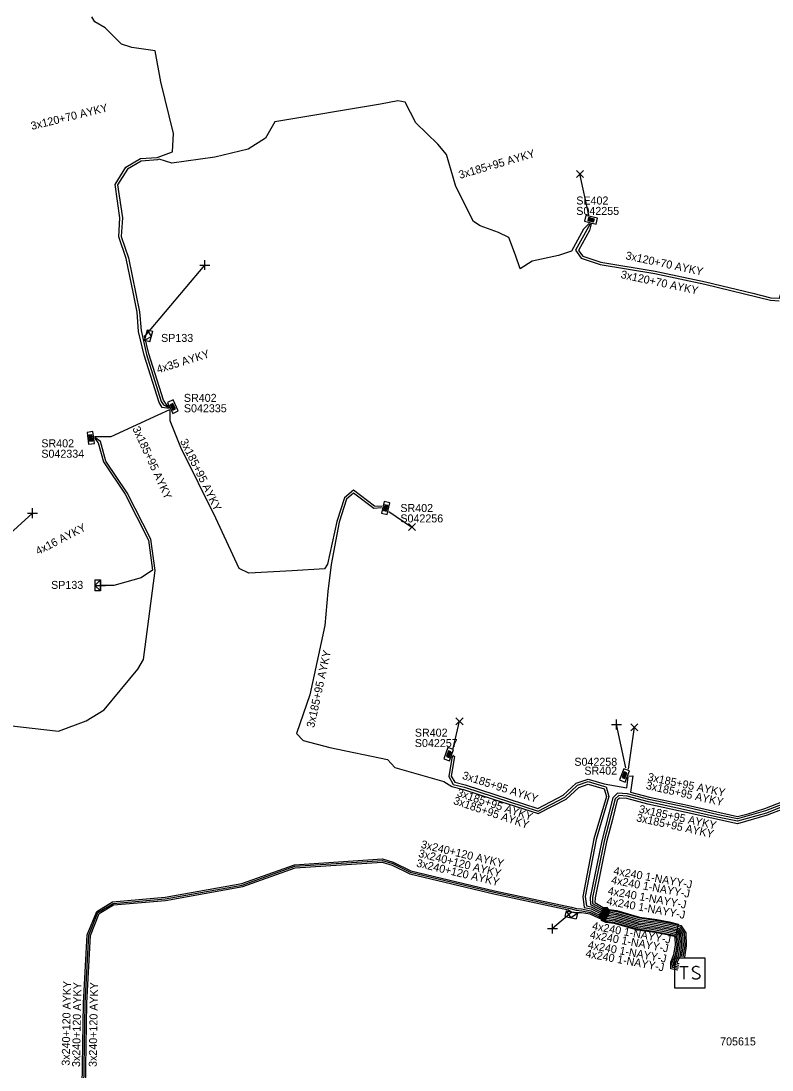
# Model space of a CAD drawing. Extents: x -748492 to -735633, y -1146251 to -1139940.
# Drawn here: x -736689.1 to -736595.2, y -1144893.5 to -1144762.4 of the extents above; entities that cross this region are included whole.
import ezdxf

# ---------------------------------------------------------------- set-up
doc = ezdxf.new("R2010")
doc.units = 0
for name, color, linetype in [('Vrstva 1', 7, 'Continuous'), ('Vrstva 19', 7, 'Continuous'), ('Vrstva 20', 7, 'Continuous'), ('Vrstva 25', 7, 'Continuous'), ('Vrstva 26', 7, 'Continuous'), ('Vrstva 28', 7, 'Continuous'), ('Vrstva 29', 7, 'Continuous'), ('Vrstva 30', 7, 'Continuous'), ('Vrstva 31', 7, 'Continuous'), ('Vrstva 33', 7, 'Continuous'), ('Vrstva 34', 7, 'Continuous'), ('Vrstva 4', 7, 'Continuous'), ('Vrstva 5', 7, 'Continuous'), ('Vrstva 52', 7, 'Continuous'), ('Vrstva 54', 7, 'Continuous'), ('Vrstva 59', 7, 'Continuous'), ('Vrstva 6', 7, 'Continuous'), ('Vrstva 8', 7, 'Continuous'), ('Vrstva 9', 7, 'Continuous')]:
    doc.layers.add(name, color=color, linetype=linetype)

# ---------------------------------------------------------------- blocks, each defined once
blk = doc.blocks.new('NN870')
at = {"layer": 'Vrstva 4'}
for points in [[(0, -0.25), (0.5, 0), (0, 0.25), (-0.5, 0), (0, -0.25)], [(0.37, 0), (0, 0.19), (-0.36, 0), (0, -0.19), (0.37, 0)], [(0.24, 0), (0, 0.12), (-0.25, 0), (0, -0.12), (0.24, 0)], [(0.12, 0), (0, 0.06), (-0.13, 0), (0, -0.06), (0.12, 0)]]:
    blk.add_lwpolyline(points, dxfattribs=at)
blk = doc.blocks.new('NN800')
at = {"layer": 'Vrstva 1'}
for points in [[(-0.44, 0.44), (0.44, -0.44)], [(-0.44, -0.44), (0.44, 0.44)]]:
    blk.add_lwpolyline(points, dxfattribs=at)
blk = doc.blocks.new('NN620')
at = {"layer": 'Vrstva 8'}
for points in [[(0.75, 0), (-0.75, 0)], [(-0.75, 0), (-0.75, -0.75)], [(0.75, -0.75), (0.75, 0)], [(-0.75, -0.75), (0.75, -0.75)], [(0.37, -0.18), (-0.38, -0.18)], [(-0.38, -0.18), (-0.38, -0.56)], [(-0.38, -0.56), (0.37, -0.56)], [(0.32, -0.23), (-0.33, -0.23)], [(-0.33, -0.23), (-0.33, -0.51)], [(-0.33, -0.51), (0.32, -0.51)], [(0.27, -0.27), (-0.28, -0.27)], [(-0.28, -0.27), (-0.28, -0.46)], [(-0.28, -0.46), (0.27, -0.46)], [(0.23, -0.32), (-0.23, -0.32)], [(-0.23, -0.32), (-0.23, -0.42)], [(-0.23, -0.42), (0.23, -0.42)], [(-0.19, -0.37), (0.19, -0.37)], [(0.23, -0.42), (0.23, -0.32)], [(0.27, -0.46), (0.27, -0.27)], [(0.32, -0.51), (0.32, -0.23)], [(0.37, -0.56), (0.37, -0.18)]]:
    blk.add_lwpolyline(points, dxfattribs=at)
blk = doc.blocks.new('NN630')
at = {"layer": 'Vrstva 9'}
for points in [[(0, -0.7), (-0.7, 0)], [(-0.7, -0.7), (-0.7, 0), (0.7, 0), (0.7, -0.7)], [(-0.7, -0.7), (0.7, -0.7)], [(0, -0.7), (0.7, 0)]]:
    blk.add_lwpolyline(points, dxfattribs=at)
blk = doc.blocks.new('NN640')
at = {"layer": 'Vrstva 6'}
for points in [[(-1.89, 1.89), (1.89, 1.89)], [(-1.89, -1.89), (-1.89, 1.89)], [(1.89, 1.89), (1.89, -1.89)], [(-1.26, 0.79), (-0.22, 0.79)], [(-0.73, 0.79), (-0.73, -0.79)], [(1.2, 0.66), (0.94, 0.79), (0.66, 0.79), (0.41, 0.66), (0.28, 0.47), (0.28, 0.41), (0.41, 0.22), (1.13, -0.16), (1.26, -0.32), (1.26, -0.47), (1.13, -0.66), (0.91, -0.79), (0.63, -0.79), (0.5, -0.73), (0.28, -0.6)], [(1.89, -1.89), (-1.89, -1.89)]]:
    blk.add_lwpolyline(points, dxfattribs=at)

msp = doc.modelspace()

# ---------------------------------------------------------------- linework, layer by layer
at = {"layer": 'Vrstva 20'}
msp.add_lwpolyline([(-736607.29, -1144876.83), (-736608.36, -1144876.57), (-736609.87, -1144876.29), (-736612.07, -1144875.98), (-736614.92, -1144875.17), (-736616.01, -1144875.02), (-736616.56, -1144874.77), (-736616.09, -1144873.22), (-736615.66, -1144873.41), (-736614.65, -1144873.55), (-736611.8, -1144874.36), (-736609.64, -1144874.67), (-736608.09, -1144874.96), (-736606.99, -1144875.22)], close=True, dxfattribs=at)
at = {"layer": 'Vrstva 5'}
for points in [[(-736670.58, -1144810.81), (-736671.47, -1144810.69), (-736671.87, -1144810.05), (-736673.71, -1144804.14), (-736674.45, -1144801.18), (-736674.59, -1144798.78), (-736675.07, -1144796.49), (-736675.96, -1144792.06), (-736676.9, -1144789.34), (-736676.75, -1144786.99), (-736677.37, -1144782.8), (-736676.01, -1144780.67), (-736674.18, -1144779.59), (-736672.12, -1144779.45), (-736670.19, -1144778.72), (-736670.05, -1144776.44), (-736671.63, -1144770), (-736672.37, -1144766.1), (-736675.28, -1144765.69), (-736676.55, -1144765.27), (-736678.61, -1144763.26), (-736679.89, -1144762.49), (-736680.26, -1144761.88)], [(-736618.11, -1144787.69), (-736618.79, -1144788.4), (-736620.3, -1144791.14), (-736621.94, -1144791.69), (-736625.23, -1144792.39), (-736626.71, -1144793.35), (-736627.32, -1144791.63), (-736628.13, -1144789.43), (-736629.45, -1144788.83), (-736631.71, -1144787.98), (-736632.54, -1144787.44), (-736634.78, -1144783.08), (-736635.95, -1144779.06), (-736637.02, -1144777.77), (-736639.77, -1144775.13), (-736641.08, -1144772.53), (-736642.01, -1144772.36), (-736644.19, -1144772.78), (-736657.4, -1144775), (-736658.55, -1144777.03), (-736660.73, -1144778.41), (-736664.91, -1144779.41), (-736670.25, -1144780.14), (-736671.86, -1144779.65), (-736672.05, -1144779.74), (-736674.08, -1144779.89), (-736675.79, -1144780.89), (-736677.05, -1144782.86), (-736676.45, -1144786.97), (-736676.6, -1144789.3), (-736675.68, -1144791.98), (-736674.29, -1144798.72), (-736674.1, -1144801.07), (-736673.42, -1144804.06), (-736671.6, -1144809.92), (-736671.3, -1144810.35), (-736670.64, -1144810.69)], [(-736617.98, -1144787.72), (-736619.81, -1144791.03), (-736619.09, -1144792.02), (-736616.72, -1144792.81), (-736609.9, -1144793.93), (-736603.63, -1144795.28), (-736595.45, -1144797.27), (-736594.33, -1144797.34)], [(-736617.85, -1144787.75), (-736618.05, -1144788.55), (-736619.45, -1144791.05), (-736618.91, -1144791.76), (-736616.64, -1144792.51), (-736609.84, -1144793.63), (-736603.57, -1144794.98), (-736597.64, -1144796.39), (-736595.41, -1144796.97), (-736594.31, -1144797.04), (-736593.31, -1144793.6), (-736593.78, -1144797.23), (-736592.02, -1144797.88), (-736586.01, -1144799.21), (-736576.41, -1144801.48), (-736570.34, -1144802.77), (-736568.81, -1144799.74)], [(-736679.92, -1144814.29), (-736677.87, -1144814.31), (-736671.98, -1144811.6), (-736670.52, -1144810.92)], [(-736644.02, -1144823.07), (-736644.93, -1144823), (-736647.56, -1144821.01), (-736648.69, -1144821.96), (-736649.64, -1144824.94), (-736650.79, -1144830.26), (-736651.17, -1144830.83), (-736655.21, -1144831.08), (-736660.66, -1144831.38), (-736661.86, -1144830.8), (-736664.78, -1144824.51), (-736669.15, -1144815.67), (-736670.49, -1144812.33), (-736670.46, -1144811.04)], [(-736761.09, -1144841.39), (-736760.78, -1144841.99), (-736759.17, -1144842.04), (-736750.14, -1144844.69), (-736741.44, -1144845.96), (-736725.38, -1144847.25), (-736714.55, -1144847.88), (-736711.66, -1144847.99), (-736711.52, -1144846.24), (-736711.16, -1144845.19), (-736711.36, -1144848.01), (-736709.95, -1144848.44), (-736701.65, -1144849.16), (-736684.43, -1144851.13), (-736680.99, -1144849.84), (-736678.74, -1144848.46), (-736674.53, -1144843.36), (-736673.79, -1144842.16), (-736672.37, -1144831.05), (-736672.88, -1144827.15), (-736675.86, -1144821.36), (-736678.52, -1144817.37), (-736679.2, -1144814.95), (-736679.9, -1144814.42)], [(-736644.05, -1144823.2), (-736645.03, -1144823.3), (-736647.54, -1144821.39), (-736648.43, -1144822.14), (-736649.34, -1144825.02), (-736650.34, -1144830.31), (-736650.77, -1144833.69), (-736651.13, -1144837.91), (-736651.6, -1144840.05), (-736653.03, -1144846.58), (-736654.69, -1144851.4), (-736653.87, -1144852.3), (-736650.52, -1144853.18), (-736643.32, -1144854.67), (-736642.38, -1144855.65), (-736636.25, -1144857.41), (-736635.27, -1144858.03), (-736633.79, -1144858.42), (-736630.08, -1144859.61), (-736624.47, -1144861.43), (-736620.98, -1144859.61), (-736619.41, -1144858.16), (-736618.22, -1144857.74), (-736616.24, -1144858.31), (-736615.95, -1144859.27), (-736617.52, -1144864.57), (-736618.89, -1144871.79), (-736618.73, -1144873.15), (-736617.87, -1144873.33), (-736616.28, -1144874.13)], [(-736635.2, -1144854.24), (-736635.25, -1144854.48), (-736635.64, -1144856.8), (-736635.08, -1144857.77), (-736633.7, -1144858.13), (-736629.99, -1144859.33), (-736624.49, -1144861.1), (-736621.15, -1144859.37), (-736619.57, -1144857.89), (-736618.22, -1144857.42), (-736616.3, -1144858), (-736615.98, -1144858.07), (-736615.63, -1144859.27), (-736617.22, -1144864.65), (-736618.59, -1144871.8), (-736618.45, -1144872.93), (-736617.85, -1144873.08), (-736616.2, -1144873.95)], [(-736635.16, -1144854.12), (-736634.92, -1144854.3), (-736635.33, -1144856.74), (-736634.88, -1144857.51), (-736633.62, -1144857.84), (-736629.9, -1144859.04), (-736624.52, -1144860.78), (-736621.33, -1144859.12), (-736619.73, -1144857.63), (-736618.23, -1144857.11), (-736616.23, -1144857.71), (-736613.39, -1144858.19), (-736613.23, -1144856.87)], [(-736613.19, -1144856.75), (-736612.66, -1144856.71), (-736612.95, -1144858.73), (-736610.56, -1144859.39), (-736605.8, -1144860.39), (-736599.57, -1144861.77), (-736598.24, -1144861.44), (-736596.15, -1144860.78), (-736593.91, -1144859.91), (-736591.07, -1144860.91), (-736587.05, -1144861.89), (-736586.45, -1144861.25), (-736585.84, -1144858.49), (-736586.05, -1144858.34)], [(-736586.02, -1144858.22), (-736585.51, -1144858.39), (-736586.17, -1144861.4), (-736586.95, -1144862.22), (-736591.16, -1144861.2), (-736593.9, -1144860.23), (-736596.05, -1144861.06), (-736599.57, -1144862.08), (-736601.98, -1144861.57), (-736605.86, -1144860.68), (-736610.63, -1144859.68), (-736613.29, -1144858.95), (-736614.54, -1144858.89), (-736615.13, -1144859.44), (-736616.52, -1144864.82), (-736617.97, -1144871.89), (-736617.95, -1144872.78), (-736616.11, -1144873.76)], [(-736593.9, -1144860.55), (-736595.95, -1144861.35), (-736599.56, -1144862.39), (-736602.04, -1144861.86), (-736605.93, -1144860.98), (-736610.7, -1144859.97), (-736613.33, -1144859.25), (-736614.4, -1144859.17), (-736614.87, -1144859.6), (-736616.22, -1144864.88), (-736617.67, -1144871.92), (-736617.69, -1144872.67), (-736616.03, -1144873.58)], [(-736558.85, -1144859.73), (-736558.46, -1144861.09), (-736562.04, -1144865.38), (-736563.53, -1144867.52), (-736568.72, -1144866.68), (-736578.62, -1144864.18), (-736584.72, -1144862.86), (-736586.37, -1144862.51), (-736586.75, -1144862.89), (-736591.33, -1144861.77), (-736593.89, -1144860.87), (-736595.86, -1144861.63), (-736599.54, -1144862.7), (-736605.99, -1144861.27), (-736610.77, -1144860.26), (-736613.38, -1144859.55), (-736614.32, -1144859.5), (-736614.6, -1144859.76), (-736615.19, -1144862.17), (-736615.93, -1144864.95), (-736617.36, -1144871.94), (-736617.38, -1144872.55), (-736615.95, -1144873.4)], [(-736679.86, -1144906.22), (-736680.09, -1144905.34), (-736682, -1144897.49), (-736681.74, -1144896.65), (-736681.46, -1144895.96), (-736681.06, -1144895.78), (-736680.89, -1144885.11), (-736680.45, -1144876.64), (-736679.34, -1144873.92), (-736677.56, -1144872.83), (-736671.06, -1144872.27), (-736661.41, -1144870.54), (-736654.87, -1144868.21), (-736643.97, -1144867.49), (-736642.73, -1144867.86), (-736640.53, -1144868.94), (-736630.03, -1144871.44), (-736620.68, -1144873.44), (-736620.25, -1144873.73)], [(-736681.76, -1144895.67), (-736681.46, -1144895.52), (-736681.29, -1144885.09), (-736680.85, -1144876.56), (-736679.66, -1144873.64), (-736677.68, -1144872.45), (-736671.12, -1144871.87), (-736661.51, -1144870.16), (-736654.95, -1144867.81), (-736643.93, -1144867.09), (-736642.59, -1144867.48), (-736640.39, -1144868.56), (-736629.93, -1144871.06), (-736620.3, -1144873.12), (-736619.68, -1144873.29), (-736619.05, -1144873.34), (-736617.9, -1144873.57), (-736616.36, -1144874.31)], [(-736681.73, -1144895.89), (-736681.26, -1144895.65), (-736681.09, -1144885.1), (-736680.65, -1144876.6), (-736679.5, -1144873.78), (-736677.62, -1144872.64), (-736671.09, -1144872.07), (-736661.46, -1144870.35), (-736654.91, -1144868.01), (-736643.95, -1144867.29), (-736642.66, -1144867.67), (-736640.46, -1144868.75), (-736629.98, -1144871.25), (-736620.49, -1144873.28), (-736619.72, -1144873.51), (-736619.01, -1144873.59), (-736617.94, -1144873.79), (-736616.44, -1144874.49)], [(-736606.15, -1144879.37), (-736605.92, -1144877.96), (-736605.99, -1144876.31), (-736606.56, -1144875.46), (-736607.38, -1144875.27), (-736608.05, -1144875.1), (-736609.62, -1144874.81), (-736610.4, -1144874.69), (-736611.77, -1144874.51), (-736614.61, -1144873.7), (-736615.59, -1144873.56), (-736615.95, -1144873.4)], [(-736607.03, -1144880.99), (-736607.89, -1144880.84), (-736607.91, -1144879.97), (-736607.52, -1144879.04), (-736607.32, -1144877.88), (-736607.37, -1144876.94), (-736607.42, -1144876.69), (-736607.7, -1144876.63), (-736608.34, -1144876.47), (-736609.86, -1144876.19), (-736610.6, -1144876.08), (-736612.05, -1144875.88), (-736614.9, -1144875.07), (-736615.98, -1144874.92), (-736617.99, -1144874.01), (-736619.05, -1144873.82), (-736619.66, -1144873.81), (-736620.25, -1144873.73)], [(-736606.98, -1144880.79), (-736607.7, -1144880.67), (-736607.71, -1144880.01), (-736607.32, -1144879.09), (-736607.12, -1144877.89), (-736607.18, -1144876.69), (-736607.29, -1144876.52), (-736607.66, -1144876.44), (-736608.3, -1144876.28), (-736609.82, -1144876), (-736610.57, -1144875.88), (-736612.01, -1144875.69), (-736614.86, -1144874.88), (-736615.93, -1144874.72), (-736616.44, -1144874.49)], [(-736606.95, -1144880.6), (-736607.5, -1144880.5), (-736607.51, -1144880.05), (-736607.13, -1144879.15), (-736606.92, -1144877.9), (-736606.98, -1144876.63), (-736607.17, -1144876.34), (-736607.61, -1144876.24), (-736608.26, -1144876.08), (-736609.79, -1144875.8), (-736610.54, -1144875.68), (-736611.97, -1144875.49), (-736614.82, -1144874.68), (-736615.87, -1144874.53), (-736616.36, -1144874.31)], [(-736606.89, -1144880.41), (-736607.3, -1144880.33), (-736607.31, -1144880.09), (-736606.94, -1144879.21), (-736606.72, -1144877.91), (-736606.78, -1144876.57), (-736607.05, -1144876.16), (-736607.56, -1144876.04), (-736608.22, -1144875.88), (-736609.76, -1144875.6), (-736610.51, -1144875.48), (-736611.93, -1144875.29), (-736614.78, -1144874.48), (-736615.81, -1144874.34), (-736616.28, -1144874.13)], [(-736606.84, -1144880.21), (-736607.11, -1144880.16), (-736607.04, -1144879.96), (-736606.74, -1144879.26), (-736606.52, -1144877.92), (-736606.59, -1144876.5), (-736606.92, -1144875.99), (-736607.52, -1144875.85), (-736608.18, -1144875.69), (-736609.72, -1144875.41), (-736610.48, -1144875.28), (-736611.89, -1144875.1), (-736614.74, -1144874.29), (-736615.76, -1144874.14), (-736616.2, -1144873.95)], [(-736606.54, -1144879.26), (-736606.32, -1144877.94), (-736606.39, -1144876.44), (-736606.8, -1144875.81), (-736607.47, -1144875.66), (-736608.13, -1144875.49), (-736609.69, -1144875.21), (-736610.45, -1144875.09), (-736611.85, -1144874.9), (-736614.7, -1144874.09), (-736615.7, -1144873.95), (-736616.11, -1144873.76)], [(-736606.35, -1144879.32), (-736606.12, -1144877.95), (-736606.19, -1144876.37), (-736606.68, -1144875.63), (-736607.43, -1144875.46), (-736608.09, -1144875.3), (-736609.66, -1144875.01), (-736610.42, -1144874.89), (-736611.81, -1144874.71), (-736614.65, -1144873.9), (-736615.65, -1144873.75), (-736616.03, -1144873.58)]]:
    msp.add_lwpolyline(points, dxfattribs=at)
at = {"layer": 'Vrstva 52'}
for points in [[(-736670.69, -1144810.57), (-736670.9, -1144810.41), (-736671.32, -1144809.78), (-736673.14, -1144803.98), (-736673.69, -1144801.74), (-736673.5, -1144801.64)], [(-736679.89, -1144814.55), (-736679.46, -1144815.11), (-736678.8, -1144817.49), (-736676.12, -1144821.52), (-736673.17, -1144827.24), (-736672.67, -1144831.01), (-736674.1, -1144831.97), (-736677.52, -1144832.94), (-736679.18, -1144832.91)]]:
    msp.add_lwpolyline(points, dxfattribs=at)
at = {"layer": 'Vrstva 59'}
for points in [[(-736618.15, -1144786.64), (-736619.25, -1144781.5)], [(-736673.5, -1144801.64), (-736666.13, -1144792.88)], [(-736711.16, -1144845.19), (-736687.69, -1144823.88)], [(-736643.13, -1144823.69), (-736640.25, -1144825.63)], [(-736635.1, -1144853.28), (-736634.31, -1144849.88)], [(-736613.5, -1144855.7), (-736614.7, -1144850.3)], [(-736613.2, -1144855.88), (-736612.44, -1144850.63)], [(-736620.25, -1144873.73), (-736622.7, -1144875.8)]]:
    msp.add_lwpolyline(points, dxfattribs=at)

# ---------------------------------------------------------------- block references
at = {"layer": 'Vrstva 19'}
for p, rotation in [((-736616.11, -1144873.76), -25.11355997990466), ((-736616.01, -1144873.58), -27.409296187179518), ((-736615.95, -1144873.4), -24.947774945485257), ((-736616.44, -1144874.49), -22.511684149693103), ((-736616.4, -1144874.29), -25.869487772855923), ((-736616.29, -1144874.13), -22.874902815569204), ((-736616.2, -1144873.95), -23.60357793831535)]:
    msp.add_blockref('NN870', p, dxfattribs=dict(at, rotation=rotation))
at = {"layer": 'Vrstva 25'}
msp.add_blockref('NN640', (-736605.52, -1144881.33), dxfattribs=at)
at = {"layer": 'Vrstva 28'}
for p, rotation in [((-736617.95, -1144787.59), 166.57176959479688), ((-736670.46, -1144810.75), 116.30779160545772), ((-736680.03, -1144814.44), -82.83727780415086), ((-736643.91, -1144823.16), 77.313713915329), ((-736635.3, -1144854.14), -109.563783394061), ((-736613.33, -1144856.77), -109.56378334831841)]:
    msp.add_blockref('NN620', p, dxfattribs=dict(at, rotation=rotation))
at = {"layer": 'Vrstva 31'}
for p, rotation in [((-736673.5, -1144801.64), 75.25643607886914), ((-736679.18, -1144832.91), -90.43139438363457), ((-736620.25, -1144873.73), -12.248921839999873)]:
    msp.add_blockref('NN630', p, dxfattribs=dict(at, rotation=rotation))
at = {"layer": 'Vrstva 34'}
for p in [(-736619.25, -1144781.5), (-736640.25, -1144825.63), (-736634.31, -1144849.88), (-736612.44, -1144850.63)]:
    msp.add_blockref('NN800', p, dxfattribs=at)
for p, rotation in [((-736666.13, -1144792.88), 45), ((-736687.69, -1144823.88), 44.99999995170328), ((-736679.18, -1144832.91), 45), ((-736614.7, -1144850.3), 44.99999995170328), ((-736622.7, -1144875.8), 44.99999995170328)]:
    msp.add_blockref('NN800', p, dxfattribs=dict(at, rotation=rotation))

# ---------------------------------------------------------------- texts
at = {"layer": 'Vrstva 26'}
msp.add_text('705615', height=1, dxfattribs=at).set_placement((-736601.73, -1144890.39))
at = {"layer": 'Vrstva 29'}
for s, p in [('S042255', (-736619.71, -1144786.62)), ('S042335', (-736668.76, -1144811.28)), ('S042334', (-736686.58, -1144816.96)), ('S042256', (-736641.7, -1144825.04)), ('S042257', (-736639.89, -1144853.11)), ('S042258', (-736619.95, -1144855.45))]:
    msp.add_text(s, height=1, dxfattribs=at).set_placement(p)
at = {"layer": 'Vrstva 30'}
for s, p in [('SE402', (-736619.71, -1144785.32)), ('SR402', (-736668.76, -1144809.98)), ('SR402', (-736686.58, -1144815.66)), ('SR402', (-736641.7, -1144823.74)), ('SR402', (-736639.89, -1144851.81)), ('SR402', (-736618.7, -1144856.56))]:
    msp.add_text(s, height=1, dxfattribs=at).set_placement(p)
at = {"layer": 'Vrstva 33'}
for p in [(-736671.61, -1144802.49), (-736685.36, -1144833.35)]:
    msp.add_text('SP133', height=1, dxfattribs=at).set_placement(p)
at = {"layer": 'Vrstva 54'}
for s, rotation, p in [('4x35 AYKY', 17.344, (-736672, -1144806.43)), ('4x16 AYKY', 27.317, (-736686.98, -1144829.14))]:
    msp.add_text(s, height=1, rotation=rotation, dxfattribs=at).set_placement(p)
at = {"layer": 'Vrstva 6'}
for s, rotation, p in [('3x120+70 AYKY', 13.786, (-736687.76, -1144776.01)), ('3x185+95 AYKY', 16.232, (-736634.25, -1144782.12)), ('3x120+70 AYKY', 347.852, (-736613.61, -1144792.14)), ('3x120+70 AYKY', 347.847, (-736614.21, -1144794.5)), ('3x185+95 AYKY', 294.707, (-736675.22, -1144813.31)), ('3x185+95 AYKY', 296.305, (-736669.27, -1144814.89)), ('3x185+95 AYKY', 77.648, (-736652.48, -1144850.76)), ('3x185+95 AYKY', 342.121, (-736634.05, -1144857.06)), ('3x185+95 AYKY', 348.135, (-736610.85, -1144857.29)), ('3x185+95 AYKY', 347.344, (-736611.06, -1144858.34)), ('3x185+95 AYKY', 341.519, (-736634.71, -1144859.21)), ('3x185+95 AYKY', 341.523, (-736635.15, -1144860.21)), ('3x185+95 AYKY', 347.636, (-736612.27, -1144862.37)), ('3x185+95 AYKY', 347.638, (-736611.95, -1144861.29)), ('3x240+120 AYKY', 346.586, (-736639.2, -1144865.7)), ('3x240+120 AYKY', 345.896, (-736639.51, -1144866.82)), ('3x240+120 AYKY', 346.579, (-736639.76, -1144868.04)), ('4x240 1-NAYY-J', 349.682, (-736615.11, -1144869.02)), ('4x240 1-NAYY-J', 349.666, (-736615.4, -1144870.17)), ('4x240 1-NAYY-J', 349.643, (-736615.83, -1144871.52)), ('4x240 1-NAYY-J', 349.663, (-736615.98, -1144872.8)), ('4x240 1-NAYY-J', 349.646, (-736617.78, -1144875.9)), ('4x240 1-NAYY-J', 349.629, (-736618.07, -1144876.99)), ('4x240 1-NAYY-J', 349.595, (-736618.61, -1144879.35)), ('4x240 1-NAYY-J', 349.612, (-736618.32, -1144878.27)), ('3x240+120 AYKY', 89.077, (-736683.04, -1144892.93)), ('3x240+120 AYKY', 89.077, (-736681.74, -1144893.1)), ('3x240+120 AYKY', 89.076, (-736679.66, -1144893.09))]:
    msp.add_text(s, height=1, rotation=rotation, dxfattribs=at).set_placement(p)

doc.saveas('drawing.dxf')
